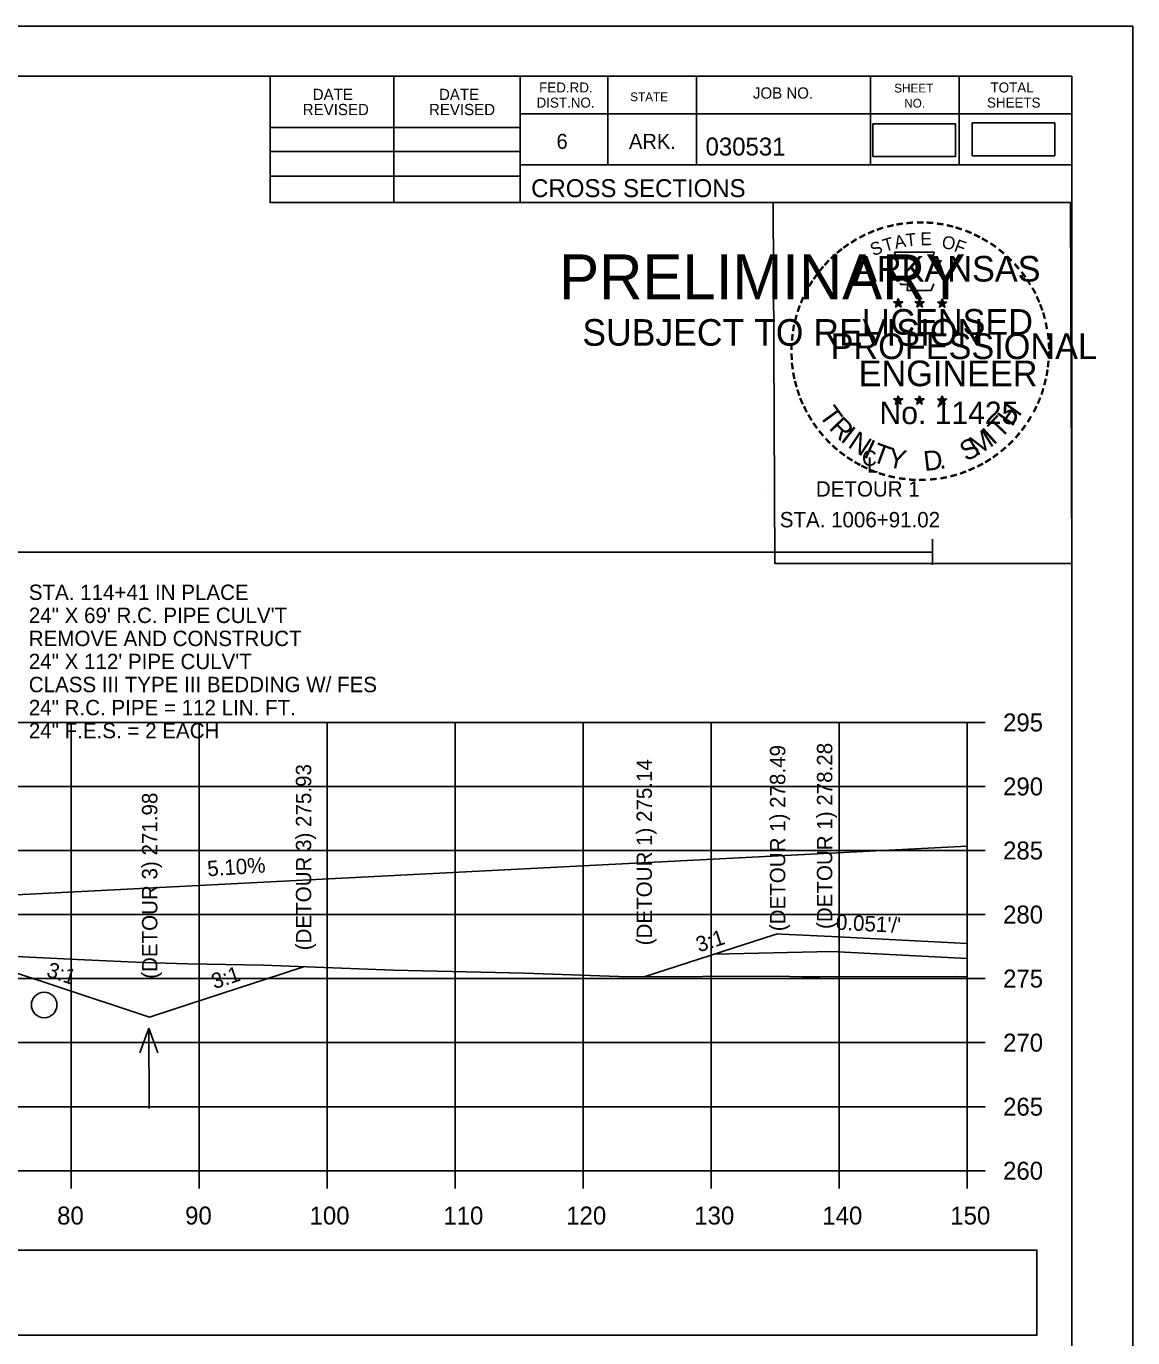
# Model space of a CAD drawing. Extents: x 285 to 4233, y -659 to 3710.
# Drawn here: x 615.8 to 702.2, y 513.8 to 616.2 of the extents above; entities that cross this region are included whole.
import ezdxf

# ---------------------------------------------------------------- set-up
doc = ezdxf.new("R2010")
doc.units = 0
for name, color, linetype in [('R_Alt Surface', 7, 'Continuous'), ('R_Axis', 7, 'Continuous'), ('R_Axis Annot', 7, 'Continuous'), ('R_Border', 7, 'Continuous'), ('R_Border PE', 7, 'Continuous'), ('R_Border Prem', 7, 'Continuous'), ('R_Detour', 7, 'Continuous'), ('R_Drive', 7, 'Continuous'), ('R_Exist Surface', 7, 'Continuous'), ('R_Grid', 7, 'Continuous'), ('R_No Plot', 7, 'Continuous'), ('R_Water', 7, 'Continuous'), ('R_Water Annot', 7, 'Continuous'), ('R_Xsect Elev', 7, 'Continuous'), ('R_Xsect Slope', 7, 'Continuous')]:
    doc.layers.add(name, color=color, linetype=linetype)

msp = doc.modelspace()

# ---------------------------------------------------------------- linework, layer by layer
at = {"layer": 'R_Alt Surface'}
for points in [[(686.56, 576.13), (686.56, 574.13)], [(539.28, 575.13), (686.56, 575.13)]]:
    msp.add_lwpolyline(points, dxfattribs=at)
at = {"layer": 'R_Axis'}
for p, q in [((689.28, 526.83), (689.28, 561.83)), ((690.68, 561.83), (689.28, 561.83)), ((690.68, 556.83), (689.28, 556.83)), ((690.68, 551.83), (689.28, 551.83)), ((690.68, 546.83), (689.28, 546.83)), ((690.68, 541.83), (689.28, 541.83)), ((690.68, 536.83), (689.28, 536.83)), ((690.68, 531.83), (689.28, 531.83)), ((389.28, 526.83), (689.28, 526.83)), ((619.28, 525.43), (619.28, 526.83)), ((629.28, 525.43), (629.28, 526.83)), ((639.28, 525.43), (639.28, 526.83)), ((649.28, 525.43), (649.28, 526.83)), ((659.28, 525.43), (659.28, 526.83)), ((669.28, 525.43), (669.28, 526.83)), ((679.28, 525.43), (679.28, 526.83)), ((689.28, 525.43), (689.28, 526.83)), ((690.68, 526.83), (689.28, 526.83))]:
    msp.add_line(p, q, dxfattribs=at)
at = {"layer": 'R_Axis Annot'}
for points in [[(681.91, 606.01), (688.36, 606.01), (688.36, 608.56), (681.91, 608.56)], [(689.66, 606.07), (696.12, 606.07), (696.12, 608.63), (689.66, 608.63)], [(554.36, 513.98), (694.72, 513.98), (694.72, 520.63), (554.36, 520.63)]]:
    msp.add_lwpolyline(points, close=True, dxfattribs=at)
at = {"layer": 'R_Border'}
for p, q in [((381.28, 612.29), (697.46, 612.29)), ((634.82, 602.41), (634.82, 612.29)), ((644.5, 602.41), (644.5, 612.29)), ((654.36, 612.29), (654.36, 602.41)), ((661.2, 612.29), (661.2, 605.35)), ((668.14, 612.29), (668.14, 605.35)), ((681.72, 612.29), (681.72, 605.35)), ((688.66, 612.29), (688.66, 605.35)), ((697.46, 406.83), (697.46, 612.29)), ((697.46, 609.35), (654.36, 609.35)), ((697.46, 609.37), (697.46, 609.37)), ((634.82, 608.27), (654.36, 608.27)), ((634.82, 606.41), (654.36, 606.41)), ((697.46, 605.35), (654.36, 605.35)), ((657.32, 605.35), (697.46, 605.35)), ((634.82, 604.47), (654.36, 604.47)), ((697.46, 602.41), (634.82, 602.41))]:
    msp.add_line(p, q, dxfattribs=at)
at = {"layer": 'R_Border PE'}
for p, q in [((683.89, 594.92), (683.85, 594.67)), ((683.89, 594.55), (683.89, 594.92)), ((683.89, 594.92), (683.94, 594.67)), ((685.56, 594.92), (685.52, 594.67)), ((685.56, 594.55), (685.56, 594.92)), ((685.56, 594.92), (685.61, 594.67)), ((683.54, 594.66), (683.89, 594.55)), ((683.54, 594.66), (683.8, 594.62)), ((683.54, 594.66), (683.78, 594.54)), ((683.68, 594.26), (683.89, 594.55)), ((683.68, 594.26), (683.8, 594.5)), ((683.68, 594.26), (683.89, 594.47)), ((684.24, 594.66), (683.89, 594.55)), ((684.11, 594.26), (683.89, 594.55)), ((684.11, 594.26), (683.89, 594.47)), ((684.24, 594.66), (683.95, 594.61)), ((684.11, 594.26), (683.97, 594.55)), ((684.24, 594.66), (684.04, 594.56)), ((685.21, 594.66), (685.56, 594.55)), ((685.21, 594.66), (685.47, 594.62)), ((685.21, 594.66), (685.45, 594.54)), ((685.35, 594.26), (685.56, 594.55)), ((685.35, 594.26), (685.47, 594.5)), ((685.35, 594.26), (685.56, 594.47)), ((685.91, 594.66), (685.56, 594.55)), ((685.78, 594.26), (685.56, 594.55)), ((685.78, 594.26), (685.56, 594.47)), ((685.91, 594.66), (685.62, 594.61)), ((685.78, 594.26), (685.64, 594.55)), ((685.91, 594.66), (685.71, 594.56)), ((686.98, 594.65), (687.33, 594.54)), ((686.98, 594.65), (687.23, 594.61)), ((686.98, 594.65), (687.22, 594.53)), ((687.11, 594.24), (687.33, 594.54)), ((687.11, 594.24), (687.24, 594.49)), ((687.11, 594.24), (687.33, 594.46)), ((687.33, 594.91), (687.29, 594.65)), ((687.33, 594.54), (687.33, 594.91)), ((687.33, 594.91), (687.38, 594.66)), ((687.67, 594.65), (687.33, 594.54)), ((687.54, 594.24), (687.33, 594.54)), ((687.54, 594.24), (687.33, 594.46)), ((687.67, 594.65), (687.39, 594.6)), ((687.54, 594.24), (687.4, 594.53)), ((687.67, 594.65), (687.47, 594.55)), ((683.54, 587.09), (683.89, 586.98)), ((683.54, 587.09), (683.79, 587.05)), ((683.54, 587.09), (683.78, 586.97)), ((683.67, 586.68), (683.89, 586.98)), ((683.67, 586.68), (683.8, 586.93)), ((683.67, 586.68), (683.89, 586.9)), ((683.89, 587.34), (683.85, 587.09)), ((683.89, 586.98), (683.89, 587.34)), ((683.89, 587.34), (683.94, 587.09)), ((684.24, 587.09), (683.89, 586.98)), ((684.1, 586.68), (683.89, 586.98)), ((684.1, 586.68), (683.89, 586.9)), ((684.24, 587.09), (683.95, 587.04)), ((684.1, 586.68), (683.97, 586.97)), ((684.24, 587.09), (684.03, 586.99)), ((685.21, 587.09), (685.56, 586.98)), ((685.21, 587.09), (685.46, 587.05)), ((685.21, 587.09), (685.45, 586.97)), ((685.34, 586.68), (685.56, 586.98)), ((685.34, 586.68), (685.47, 586.93)), ((685.34, 586.68), (685.56, 586.9)), ((685.56, 587.34), (685.52, 587.09)), ((685.56, 586.98), (685.56, 587.34)), ((685.56, 587.34), (685.61, 587.09)), ((685.91, 587.09), (685.56, 586.98)), ((685.77, 586.68), (685.56, 586.98)), ((685.77, 586.68), (685.56, 586.9)), ((685.91, 587.09), (685.62, 587.04)), ((685.77, 586.68), (685.63, 586.97)), ((685.91, 587.09), (685.7, 586.99)), ((686.98, 587.08), (687.33, 586.97)), ((686.98, 587.08), (687.23, 587.04)), ((686.98, 587.08), (687.21, 586.96)), ((687.11, 586.67), (687.33, 586.97)), ((687.11, 586.67), (687.24, 586.92)), ((687.11, 586.67), (687.32, 586.89)), ((687.33, 587.33), (687.28, 587.08)), ((687.54, 586.67), (687.32, 586.89)), ((687.33, 586.97), (687.33, 587.33)), ((687.33, 587.33), (687.37, 587.08)), ((687.67, 587.08), (687.33, 586.97)), ((687.54, 586.67), (687.33, 586.97)), ((687.67, 587.08), (687.39, 587.03)), ((687.54, 586.67), (687.4, 586.96)), ((687.67, 587.08), (687.47, 586.98))]:
    msp.add_line(p, q, dxfattribs=at)
for points in [[(683.59, 598.54), (683.85, 597.71)], [(687.1, 597.62), (687.24, 597.9), (686.55, 597.88), (686.7, 598.54), (683.59, 598.54)], [(684.08, 596.12), (684.08, 596.03), (684.64, 596.01), (684.59, 595.54), (686.46, 595.54), (686.66, 596.08)], [(683.89, 594.92), (684.11, 594.26), (683.54, 594.66), (684.24, 594.66), (683.68, 594.26), (683.89, 594.92)], [(685.56, 594.92), (685.78, 594.26), (685.21, 594.66), (685.91, 594.66), (685.35, 594.26), (685.56, 594.92)], [(687.33, 594.91), (687.54, 594.24), (686.98, 594.65), (687.67, 594.65), (687.11, 594.24), (687.33, 594.91)], [(683.89, 587.34), (684.1, 586.68), (683.54, 587.09), (684.24, 587.09), (683.67, 586.68), (683.89, 587.34)], [(685.56, 587.34), (685.77, 586.68), (685.21, 587.09), (685.91, 587.09), (685.34, 586.68), (685.56, 587.34)], [(687.33, 587.33), (687.54, 586.67), (686.98, 587.08), (687.67, 587.08), (687.11, 586.67), (687.33, 587.33)]]:
    msp.add_lwpolyline(points, dxfattribs=at)
for centre, radius in [((683.89, 594.55), 0.172), ((683.89, 594.55), 0.145), ((683.89, 594.55), 0.116), ((683.89, 594.55), 0.0991), ((683.89, 594.55), 0.0747), ((683.89, 594.55), 0.0495), ((683.89, 594.55), 0.0296), ((685.56, 594.55), 0.172), ((685.56, 594.55), 0.145), ((685.56, 594.55), 0.116), ((685.56, 594.55), 0.0991), ((685.56, 594.55), 0.0747), ((685.56, 594.55), 0.0495), ((685.56, 594.55), 0.0296), ((687.33, 594.54), 0.172), ((687.33, 594.54), 0.145), ((687.33, 594.54), 0.116), ((687.33, 594.54), 0.0991), ((687.33, 594.54), 0.0747), ((687.33, 594.54), 0.0495), ((687.33, 594.54), 0.0296), ((683.89, 586.98), 0.172), ((683.89, 586.98), 0.145), ((683.89, 586.98), 0.116), ((683.89, 586.98), 0.0991), ((683.89, 586.98), 0.0747), ((683.89, 586.98), 0.0495), ((683.89, 586.98), 0.0296), ((685.56, 586.98), 0.172), ((685.56, 586.98), 0.145), ((685.56, 586.98), 0.116), ((685.56, 586.98), 0.0991), ((685.56, 586.98), 0.0747), ((685.56, 586.98), 0.0495), ((685.56, 586.98), 0.0296), ((687.32, 586.97), 0.172), ((687.32, 586.97), 0.145), ((687.32, 586.97), 0.116), ((687.32, 586.97), 0.0991), ((687.32, 586.97), 0.0747), ((687.32, 586.97), 0.0495), ((687.32, 586.97), 0.0296)]:
    msp.add_circle(centre, radius, dxfattribs=at)
at = {"layer": 'R_Detour'}
for points in [[(585.15, 544.5), (585.68, 544.68), (587.09, 545.14), (590.03, 544.96), (591.15, 544.9), (603.32, 544.18), (605.33, 544.06), (606.37, 544), (606.85, 543.97), (610.43, 543.76), (617.95, 541.28), (625.42, 538.81), (627.3, 539.43), (632.33, 541.08), (634.42, 541.77), (637.44, 542.76)], [(664.05, 541.97), (673.55, 545.03), (674.47, 545.32), (674.79, 545.31), (678.68, 545.11), (684.2, 544.83), (689.28, 544.57)], [(669.53, 543.73), (678.68, 543.94), (689.28, 543.39)]]:
    msp.add_lwpolyline(points, dxfattribs=at)
at = {"layer": 'R_Drive'}
msp.add_line((689.28, 552.16), (577.27, 546.43), dxfattribs=at)
at = {"layer": 'R_Exist Surface'}
msp.add_lwpolyline([(609.07, 543.83), (620.33, 543.29), (624.89, 543.09), (628.39, 542.97), (634.31, 542.88), (644.47, 542.48), (654.71, 542.25), (662.76, 541.96), (674.45, 542.03), (676.4, 541.97), (676.6, 541.97), (677.78, 541.97), (688.39, 541.99), (689.28, 541.98)], dxfattribs=at)
at = {"layer": 'R_Grid'}
for p, q in [((389.28, 561.83), (689.28, 561.83)), ((619.28, 526.83), (619.28, 561.83)), ((629.28, 526.83), (629.28, 561.83)), ((639.28, 526.83), (639.28, 561.83)), ((649.28, 526.83), (649.28, 561.83)), ((659.28, 526.83), (659.28, 561.83)), ((669.28, 526.83), (669.28, 561.83)), ((679.28, 526.83), (679.28, 561.83)), ((689.28, 526.83), (689.28, 561.83)), ((389.28, 556.83), (689.28, 556.83)), ((389.28, 551.83), (689.28, 551.83)), ((389.28, 546.83), (689.28, 546.83)), ((389.28, 541.83), (689.28, 541.83)), ((389.28, 536.83), (689.28, 536.83)), ((389.28, 531.83), (689.28, 531.83)), ((389.28, 526.83), (689.28, 526.83))]:
    msp.add_line(p, q, dxfattribs=at)
at = {"layer": 'R_No Plot'}
for p, q in [((368.88, 616.18), (702.21, 616.18)), ((673.49, 579.95), (673.49, 579.95))]:
    msp.add_line(p, q, dxfattribs=at)
for points in [[(368.87, 616.18), (702.21, 616.18), (702.21, 402.85), (368.87, 402.85)], [(615.2, 612.29), (634.82, 612.29), (634.82, 602.41), (650.93, 602.41), (674.13, 602.41), (674.25, 574.25), (697.46, 574.25), (697.46, 406.83), (381.28, 406.83), (381.28, 612.29)], [(674.13, 602.41), (697.34, 602.41), (697.46, 574.25), (674.25, 574.25)]]:
    msp.add_lwpolyline(points, close=True, dxfattribs=at)
at = {"layer": 'R_Water'}
msp.add_circle((617.18, 539.77), 1, dxfattribs=at)
at = {"layer": 'R_Water Annot'}
for p, q in [((625.35, 537.96), (624.65, 536.03)), ((625.37, 531.68), (625.35, 537.96)), ((625.35, 537.96), (626.05, 536.04))]:
    msp.add_line(p, q, dxfattribs=at)

# ---------------------------------------------------------------- texts
at = {"layer": 'R_Alt Surface'}
for s, height, p in [('C', 1.2, (681.06, 581.86)), ('L', 1.2, (681.45, 581.33)), ('DETOUR 1', 1.199, (677.46, 579.46)), ('STA. 1006+91.02', 1.1985, (674.64, 577.06))]:
    msp.add_text(s, height=height, dxfattribs=at).set_placement(p)
at = {"layer": 'R_Axis Annot'}
for s, p in [('295', (692.08, 561.13)), ('290', (692.08, 556.13)), ('285', (692.08, 551.13)), ('280', (692.08, 546.13)), ('275', (692.08, 541.13)), ('270', (692.08, 536.13)), ('265', (692.08, 531.13)), ('260', (692.08, 526.13)), ('80', (618.19, 522.63)), ('90', (628.19, 522.63)), ('100', (637.91, 522.63)), ('110', (648.36, 522.63)), ('120', (657.96, 522.63)), ('130', (667.96, 522.63)), ('140', (677.96, 522.63)), ('150', (687.96, 522.63))]:
    msp.add_text(s, height=1.4, dxfattribs=at).set_placement(p)
at = {"layer": 'R_Border'}
for s, height, p in [('DATE', 0.879, (638.16, 610.42)), ('DATE', 0.879, (648.02, 610.42)), ('FED.RD.', 0.782, (655.84, 611.01)), ('JOB NO.', 0.879, (672.54, 610.53)), ('SHEET', 0.684, (683.58, 611.01)), ('TOTAL', 0.782, (691.1, 611.01)), ('DIST.NO.', 0.782, (655.64, 609.83)), ('STATE', 0.684, (662.96, 610.33)), ('NO.', 0.684, (684.36, 609.83)), ('SHEETS', 0.782, (690.82, 609.83)), ('REVISED', 0.879, (637.38, 609.24)), ('REVISED', 0.879, (647.24, 609.24)), ('6', 1.17, (657.2, 606.61)), ('ARK.', 1.172, (662.86, 606.61)), ('030531', 1.4, (668.84, 606.09)), ('CROSS SECTIONS', 1.4, (655.22, 602.84))]:
    msp.add_text(s, height=height, rotation=360, dxfattribs=at).set_placement(p)
at = {"layer": 'R_Border PE'}
for s, height, rotation, p in [('-', 1.6, 24.3072, (681.7, 599.4)), ('-', 1.6, 19.1761, (682.33, 599.67)), ('-', 1.6, 13.6301, (683.08, 599.91)), ('-', 1.6, 10.2193, (683.76, 600.07)), ('T', 1, 6.0228, (684.53, 598.97)), ('-', 1.6, 5.8968, (684.49, 600.18)), ('-', 1.6, 0.1862, (685.26, 600.25)), ('E', 1, 0.8323, (685.63, 599.08)), ('-', 1.6, 357.743, (685.98, 600.24)), ('-', 1.6, 352.1617, (686.73, 600.18)), ('-', 1.6, 347.2049, (687.45, 600.07)), ('-', 1.6, 342.3362, (688.08, 599.92)), ('-', 1.6, 337.8551, (688.82, 599.69)), ('-', 1.6, 36.2317, (679.89, 598.32)), ('-', 1.6, 34.0636, (680.47, 598.71)), ('-', 1.6, 28.7918, (681.07, 599.08)), ('S', 1, 21.594, (681.94, 598.22)), ('T', 1, 16.4036, (682.85, 598.55)), ('A', 1, 11.2132, (683.68, 598.8)), ('O', 1, 350.4515, (687.24, 598.87)), ('F', 1, 340.0707, (688.19, 598.64)), ('-', 1.6, 334.1211, (689.45, 599.42)), ('-', 1.6, 329.6409, (690.03, 599.14)), ('-', 1.6, 325.8627, (690.67, 598.78)), ('-', 1.6, 42.9622, (678.98, 597.52)), ('-', 1.6, 38.9507, (679.41, 597.94)), ('ARKANSAS', 2, 360, (680.44, 596.25)), ('-', 1.6, 320.5297, (691.28, 598.35)), ('-', 1.6, 315.5786, (691.88, 597.86)), ('-', 1.6, 50.6142, (678.13, 596.56)), ('-', 1.6, 48.423, (678.53, 597.04)), ('-', 1.6, 309.8797, (692.45, 597.31)), ('-', 1.6, 306.6522, (692.97, 596.71)), ('-', 1.6, 58.0706, (677.39, 595.46)), ('-', 1.6, 54.2325, (677.72, 595.99)), ('-', 1.4, 303.6753, (693.46, 596.14)), ('-', 1.6, 67.7743, (676.82, 594.24)), ('-', 1.6, 62.8713, (677.08, 594.85)), ('-', 1.6, 299.6684, (693.78, 595.54)), ('-', 1.6, 294.6628, (694.1, 594.92)), ('-', 1.6, 72.3945, (676.6, 593.61)), ('LICENSED', 2, 360, (681.04, 592.1)), ('DWB', 0.01, 360, (683.88, 594.55)), ('DWB', 0.01, 360, (685.55, 594.55)), ('DWB', 0.01, 360, (687.31, 594.54)), ('-', 1.6, 290.5728, (694.36, 594.35)), ('-', 1.6, 81.2013, (676.27, 592.18)), ('-', 1.6, 75.461, (676.4, 592.9)), ('-', 1.6, 285.1233, (694.59, 593.77)), ('-', 1.6, 280.5493, (694.79, 593.03)), ('-', 1.6, 85.1863, (676.2, 591.49)), ('PROFESSIONAL', 2, 360, (678.61, 590.2)), ('-', 1.6, 276.5962, (694.96, 592.26)), ('-', 1.6, 89.0622, (676.17, 590.79)), ('-', 1.6, 274.3301, (695.02, 591.54)), ('-', 1.6, 94.1959, (676.21, 590.07)), ('-', 1.6, 98.9479, (676.28, 589.4)), ('ENGINEER', 2, 360, (680.8, 588.08)), ('-', 1.6, 263.5172, (695.03, 590.24)), ('-', 1.6, 269.9407, (695.05, 590.9)), ('-', 1.6, 101.7149, (676.41, 588.67)), ('-', 1.6, 260.9953, (694.96, 589.58)), ('-', 1.6, 105.4578, (676.58, 588.07)), ('-', 1.6, 109.0874, (676.79, 587.44)), ('-', 1.6, 252.8681, (694.67, 588.19)), ('-', 1.6, 255.7626, (694.85, 588.91)), ('-', 1.6, 114.0643, (677.04, 586.84)), ('No. 11425', 1.757, 360, (682.43, 585.12)), ('DWB', 0.01, 360, (683.88, 586.97)), ('DWB', 0.01, 360, (685.55, 586.97)), ('DWB', 0.01, 360, (687.31, 586.96)), ('H', 1.54, 54.6088, (692.77, 584.85)), ('-', 1.6, 247.8887, (694.45, 587.51)), ('-', 1.6, 115.7289, (677.35, 586.23)), ('-', 1.6, 120.4471, (677.71, 585.64)), ('T', 1.54, 306.0406, (677.65, 585.82)), ('R', 1.54, 314.005, (678.41, 584.77)), ('T', 1.54, 46.6444, (691.88, 583.91)), ('-', 1.6, 239.0712, (693.79, 586.13)), ('-', 1.6, 244.6197, (694.18, 586.88)), ('-', 1.6, 125.8934, (678.11, 585.08)), ('I', 1.54, 321.9694, (679.31, 583.84)), ('M', 1.54, 32.6563, (690.03, 582.59)), ('I', 1.54, 42.1136, (691.32, 583.43)), ('-', 1.6, 233.8452, (693.39, 585.48)), ('-', 1.6, 130.7181, (678.57, 584.53)), ('-', 1.6, 134.2238, (679.09, 583.98)), ('N', 1.54, 326.5002, (679.88, 583.37)), ('I', 1.54, 335.3603, (681.09, 582.58)), ('T', 1.54, 339.8912, (681.75, 582.25)), ('S', 1.54, 26.9312, (689.19, 582.18)), ('-', 1.6, 225.7653, (692.48, 584.35)), ('-', 1.6, 231.2538, (692.96, 584.91)), ('-', 1.6, 138.9338, (679.61, 583.52)), ('-', 1.6, 144.6463, (680.17, 583.11)), ('Y', 1.54, 347.8556, (682.97, 581.81)), ('D', 1.54, 6.3969, (685.95, 581.45)), ('-', 1.6, 215.7363, (691.41, 583.37)), ('-', 1.6, 221.0851, (691.96, 583.84)), ('-', 1.6, 148.0898, (680.73, 582.74)), ('-', 1.6, 151.5704, (681.31, 582.42)), ('-', 1.6, 154.6002, (681.83, 582.17)), ('-', 1.6, 158.5612, (682.46, 581.91)), ('.', 1.54, 13.7642, (687.14, 581.58)), ('-', 1.6, 204.2516, (689.69, 582.32)), ('-', 1.6, 207.3568, (690.32, 582.63)), ('-', 1.6, 212.2491, (690.87, 582.98)), ('-', 1.6, 162.7983, (683.14, 581.7)), ('-', 1.6, 167.5555, (683.86, 581.54)), ('-', 1.6, 173.1155, (684.63, 581.43)), ('-', 1.6, 176.5183, (685.38, 581.37)), ('-', 1.6, 181.5918, (686.12, 581.39)), ('-', 1.6, 185.8167, (686.93, 581.47)), ('-', 1.6, 191.2858, (687.67, 581.6)), ('-', 1.6, 195.4743, (688.4, 581.8)), ('-', 1.6, 200.7184, (689.07, 582.04))]:
    msp.add_text(s, height=height, rotation=rotation, dxfattribs=at).set_placement(p)
at = {"layer": 'R_Border Prem'}
for s, height, p in [('PRELIMINARY', 3.5, (657.41, 594.87)), ('DWB', 0.01, (658.16, 596.72)), ('SUBJECT TO REVISION', 2.0751, (659.22, 591.24))]:
    msp.add_text(s, height=height, rotation=360, dxfattribs=at).set_placement(p)
at = {"layer": 'R_Water Annot'}
for s, p in [('STA. 114+41 IN PLACE', (615.98, 571.39)), ('24" X 69\' R.C. PIPE CULV\'T', (615.98, 569.59)), ('REMOVE AND CONSTRUCT', (615.98, 567.79)), ('24" X 112\' PIPE CULV\'T', (615.98, 565.99)), ('CLASS III TYPE III BEDDING W/ FES', (615.98, 564.19)), ('24" R.C. PIPE = 112 LIN. FT.', (615.98, 562.39)), ('24" F.E.S. = 2 EACH', (615.98, 560.59))]:
    msp.add_text(s, height=1.2, dxfattribs=at).set_placement(p)
at = {"layer": 'R_Xsect Elev'}
for s, rotation, p in [('(DETOUR 1) 278.28', 90, (678.74, 545.7)), ('(DETOUR 1) 278.49', 90, (675.07, 545.53)), ('(DETOUR 3) 275.93', 90, (638.04, 544.04)), ('(DETOUR 1) 275.14', 90, (664.65, 544.43)), ('(DETOUR 3) 271.98', 90, (626.02, 541.81)), ('5.10%', 3.8575, (629.96, 549.81))]:
    msp.add_text(s, height=1.2, rotation=rotation, dxfattribs=at).set_placement(p)
at = {"layer": 'R_Xsect Slope'}
for s, rotation, p in [("0.051'/'", 357.0954, (679, 545.65)), ('3:1', 17.8373, (668.32, 543.87)), ('3:1', 341.7249, (617.29, 542.02)), ('3:1', 18.191, (630.48, 541))]:
    msp.add_text(s, height=1.2, rotation=rotation, dxfattribs=at).set_placement(p)

doc.saveas('drawing.dxf')
